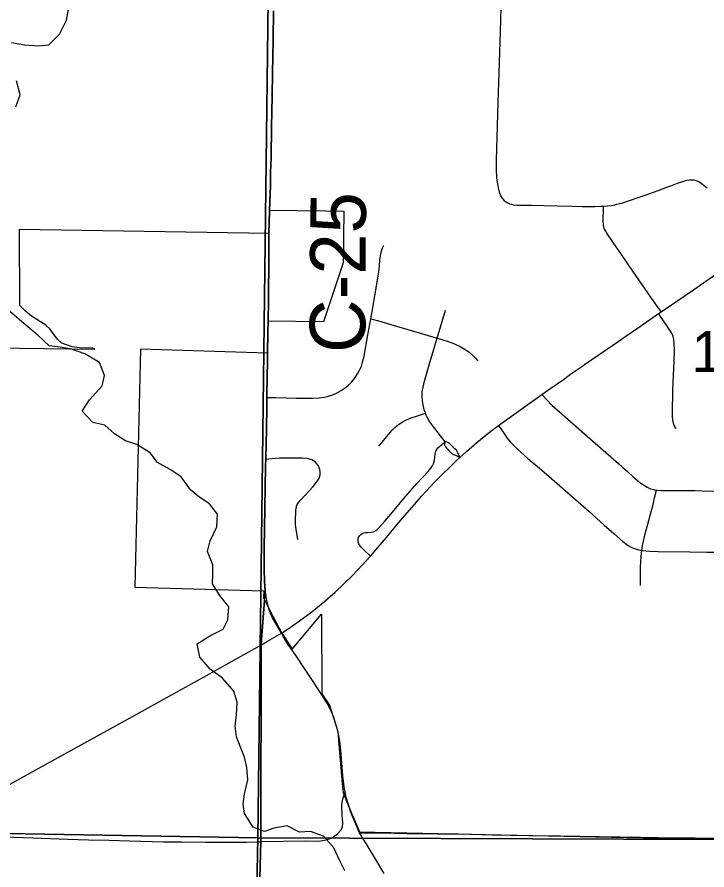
# Model space of a CAD drawing. Extents: x 0 to 34, y 0 to 22.
# Drawn here: x 6.439 to 7.145, y 18.41 to 19.283 of the extents above; entities that cross this region are included whole.
import ezdxf

# ---------------------------------------------------------------- set-up
doc = ezdxf.new("R2010")
doc.units = 0
for name, color, linetype in [('GM_X_City_Street', 7, 'Continuous'), ('GM_X_County_Road', 7, 'Continuous'), ('GM_X_County_Road_Text', 7, 'Continuous'), ('GM_X_County_Text', 7, 'Continuous'), ('GM_X_Minor_River', 7, 'Continuous'), ('GM_X_Section', 7, 'Continuous'), ('GM_X_Section_Text', 7, 'Continuous'), ('GM_X_Township_Road', 7, 'Continuous'), ('GM_X_US_Route', 7, 'Continuous')]:
    doc.layers.add(name, color=color, linetype=linetype)

msp = doc.modelspace()

# ---------------------------------------------------------------- linework, layer by layer
at = {"layer": 'GM_X_City_Street'}
for points in [[(6.93583, 19.09757), (6.93419, 19.10048), (6.93312, 19.10329), (6.93214, 19.1068), (6.93106, 19.11221), (6.93017, 19.11894), (6.9297, 19.12739), (6.92969, 19.1372), (6.9302, 19.1598), (6.93142, 19.19647), (6.93235, 19.2263), (6.93367, 19.26856), (6.9345, 19.29341)], [(6.93583, 19.09757), (6.93672, 19.09643), (6.93762, 19.09547), (6.93833, 19.09492), (6.93948, 19.09416), (6.94067, 19.09344), (6.94199, 19.09285), (6.94342, 19.09225), (6.94509, 19.09178), (6.94701, 19.09135), (6.95012, 19.09094), (6.95364, 19.09083), (6.95711, 19.09077), (6.96165, 19.09071), (6.96562, 19.09073), (6.99178, 19.09011), (7.00669, 19.08974), (7.01726, 19.08943), (7.03029, 19.08948), (7.03673, 19.0897), (7.03918, 19.08988), (7.04324, 19.09019), (7.04689, 19.09062), (7.0487, 19.09088), (7.05072, 19.09126), (7.0529, 19.09178), (7.05883, 19.09342), (7.06591, 19.09571), (7.07353, 19.09833), (7.07869, 19.10007), (7.08289, 19.1016), (7.09052, 19.10433), (7.09525, 19.10606), (7.1039, 19.10932), (7.10802, 19.11072), (7.11499, 19.11328), (7.12034, 19.11523), (7.12456, 19.1165), (7.12713, 19.11684), (7.13039, 19.11683), (7.13164, 19.11668), (7.13299, 19.11644), (7.13488, 19.11594), (7.13668, 19.11508), (7.1404, 19.11253), (7.1453, 19.10877)], [(7.09828, 18.98171), (7.09697, 18.98354), (7.09075, 18.99228), (7.0692, 19.02338), (7.05759, 19.04024), (7.04913, 19.05251), (7.04319, 19.06127), (7.04098, 19.06511), (7.04035, 19.0664), (7.03992, 19.06743), (7.03958, 19.06854), (7.03929, 19.06999), (7.03906, 19.07163), (7.03896, 19.0732), (7.03896, 19.07883), (7.03905, 19.08348), (7.03918, 19.08988)], [(6.6949, 18.89394), (6.70371, 18.89378), (6.72486, 18.89342), (6.74166, 18.89331), (6.7485, 18.89359), (6.75344, 18.8942), (6.75769, 18.89515), (6.76182, 18.89652), (6.76579, 18.8983), (6.77069, 18.90104), (6.77481, 18.90381), (6.77818, 18.90658), (6.78123, 18.90968), (6.78435, 18.91356), (6.78749, 18.91821), (6.7896, 18.92202), (6.79133, 18.92601), (6.79267, 18.93015), (6.79413, 18.93621), (6.79809, 18.95826), (6.80104, 18.9746), (6.8024, 18.98216), (6.80781, 19.01407), (6.80916, 19.02267), (6.8099, 19.02885), (6.81035, 19.03504), (6.81116, 19.04056), (6.81197, 19.04421), (6.81323, 19.04772), (6.81437, 19.04993)], [(6.87714, 18.84857), (6.8724, 18.85468), (6.86425, 18.86544), (6.86092, 18.87002), (6.85896, 18.87328), (6.85731, 18.87671), (6.8569, 18.87779), (6.85597, 18.88028), (6.85483, 18.88457), (6.85392, 18.89019), (6.8536, 18.89524), (6.85374, 18.89967), (6.85447, 18.90468), (6.85596, 18.91079), (6.86152, 18.92989), (6.86887, 18.95474), (6.8767, 18.98109), (6.87736, 18.98348)], [(7.11345, 18.86208), (7.11312, 18.86261), (7.1117, 18.86538), (7.1109, 18.86773), (7.11028, 18.87077), (7.10991, 18.87511), (7.10986, 18.88381), (7.11013, 18.89561), (7.11015, 18.89992), (7.11017, 18.90301), (7.11036, 18.90798), (7.11077, 18.91729), (7.11105, 18.9235), (7.11143, 18.93158), (7.11177, 18.94213), (7.11168, 18.94958), (7.11132, 18.95329), (7.1106, 18.9563), (7.1094, 18.95916), (7.10726, 18.96295), (7.10383, 18.96814), (7.09766, 18.97676), (7.0955, 18.97979)], [(6.80104, 18.9746), (6.80784, 18.97264), (6.82154, 18.96868), (6.85066, 18.96), (6.86887, 18.95474), (6.87151, 18.95398), (6.88218, 18.95073), (6.8868, 18.94893), (6.89238, 18.94624), (6.89666, 18.94373), (6.90124, 18.94054), (6.90504, 18.93736), (6.9081, 18.93429), (6.91043, 18.93139)], [(6.97625, 18.89693), (6.98675, 18.88568), (6.99405, 18.87914), (7.00862, 18.86652), (7.02261, 18.8542), (7.03341, 18.84482), (7.05502, 18.82608), (7.05635, 18.82475), (7.05685, 18.82438), (7.05816, 18.82304), (7.05912, 18.82227), (7.06134, 18.82007), (7.06369, 18.81806), (7.06422, 18.81773), (7.06931, 18.81314), (7.07643, 18.80706), (7.07998, 18.8044), (7.08383, 18.80215), (7.08734, 18.80057), (7.09041, 18.79962), (7.09234, 18.79917), (7.09338, 18.79904), (7.09419, 18.79895), (7.09861, 18.79868), (7.11358, 18.79865), (7.12361, 18.79875), (7.13297, 18.79858), (7.14031, 18.79843), (7.19938, 18.79786)], [(6.8092, 18.84399), (6.82264, 18.86017), (6.8261, 18.8637), (6.82942, 18.86646), (6.83305, 18.86881), (6.83689, 18.87081), (6.84147, 18.87268), (6.84969, 18.8754), (6.8569, 18.87779)], [(6.93157, 18.86522), (6.9371, 18.85742), (6.94068, 18.85235), (6.94369, 18.84865), (6.94616, 18.84611), (6.94955, 18.84279), (6.95427, 18.83823), (6.96163, 18.83161), (6.97362, 18.82163), (6.98072, 18.81554), (7.02425, 18.77746), (7.03998, 18.76332), (7.04966, 18.75458), (7.0591, 18.74656), (7.06449, 18.74248), (7.06759, 18.74063), (7.07092, 18.73925), (7.075, 18.73802), (7.07834, 18.73738), (7.07918, 18.73722), (7.08647, 18.73657), (7.09518, 18.7363), (7.12752, 18.73602), (7.14492, 18.7357), (7.1928, 18.73565)], [(6.80061, 18.73154), (6.79363, 18.7383), (6.79185, 18.74003), (6.78976, 18.74236), (6.78879, 18.74396), (6.78817, 18.74571), (6.78795, 18.74755), (6.78805, 18.74877), (6.78856, 18.75056), (6.78945, 18.75221), (6.79068, 18.7536), (6.79219, 18.75467), (6.79391, 18.75536), (6.79512, 18.75562), (6.79762, 18.75578), (6.80136, 18.75596), (6.80377, 18.75654), (6.806, 18.75761), (6.80749, 18.75872), (6.8093, 18.76043), (6.81544, 18.76749), (6.82163, 18.7745), (6.83266, 18.788), (6.8391, 18.79563), (6.84559, 18.80318), (6.84808, 18.80596), (6.85965, 18.8182), (6.86246, 18.82153), (6.86387, 18.82356), (6.86526, 18.82632), (6.86612, 18.8293), (6.86697, 18.83613), (6.86768, 18.83915), (6.86848, 18.84081), (6.86956, 18.84229), (6.87714, 18.84857)], [(6.89221, 18.83259), (6.88802, 18.83442), (6.88616, 18.83533), (6.88478, 18.83608), (6.88372, 18.83688), (6.88271, 18.8379), (6.87785, 18.84331), (6.87715, 18.84414), (6.87677, 18.8451), (6.87667, 18.84597), (6.87685, 18.84732), (6.87714, 18.84857)], [(6.89221, 18.83259), (6.89172, 18.8337), (6.89014, 18.83734), (6.88945, 18.83863), (6.88902, 18.83932), (6.88859, 18.83989), (6.88696, 18.84155), (6.88529, 18.84322), (6.88207, 18.84636), (6.8806, 18.84757), (6.87994, 18.84793), (6.87915, 18.84824), (6.87807, 18.8485), (6.87714, 18.84857)], [(6.72616, 18.74851), (6.72452, 18.75903), (6.72428, 18.76116), (6.72409, 18.7639), (6.72403, 18.76724), (6.72402, 18.77108), (6.72418, 18.77491), (6.72439, 18.77809), (6.72461, 18.7805), (6.72483, 18.78172), (6.72511, 18.78276), (6.72576, 18.78435), (6.7263, 18.78531), (6.72698, 18.78636), (6.72925, 18.78921), (6.74188, 18.80289), (6.74558, 18.8072), (6.7474, 18.80989), (6.74849, 18.81232), (6.74909, 18.81491), (6.74919, 18.81756), (6.74883, 18.8202), (6.74825, 18.8221), (6.7474, 18.82391), (6.74589, 18.8261), (6.74402, 18.82799), (6.7424, 18.82916), (6.74062, 18.83008), (6.73813, 18.83093), (6.73556, 18.83139), (6.73114, 18.83168), (6.71619, 18.83185), (6.70744, 18.83182), (6.70302, 18.83144), (6.6937, 18.83063)], [(7.0771, 18.70146), (7.07718, 18.72012), (7.07771, 18.7313), (7.07834, 18.73738), (7.07915, 18.74239), (7.08191, 18.75452), (7.09028, 18.78576), (7.09155, 18.7912), (7.09338, 18.79904)]]:
    msp.add_lwpolyline(points, dxfattribs=at)
at = {"layer": 'GM_X_County_Road'}
for p, q in [((7.0955, 18.97979), (7.09828, 18.98171)), ((6.79737, 18.4355), (6.78956, 18.44837))]:
    msp.add_line(p, q, dxfattribs=at)
for points in [[(6.69754, 19.08495), (6.6982, 19.10325), (6.69842, 19.10864), (6.69864, 19.11426), (6.69864, 19.12021), (6.69872, 19.12543), (6.69881, 19.12978), (6.69919, 19.14053), (6.6994, 19.15119), (6.69951, 19.15815), (6.69961, 19.1641), (6.69972, 19.1696), (6.69974, 19.1751), (6.69984, 19.18131), (6.6999, 19.18565), (6.70002, 19.19124), (6.70015, 19.19683), (6.70026, 19.20179), (6.70035, 19.20676), (6.70045, 19.21172), (6.70054, 19.21606), (6.7006, 19.21916), (6.70065, 19.22226), (6.70068, 19.22597), (6.70076, 19.23218), (6.70083, 19.23589), (6.7009, 19.23961), (6.70099, 19.24396), (6.70107, 19.2483), (6.70115, 19.25327), (6.70121, 19.25761), (6.70128, 19.26382), (6.70138, 19.27065), (6.70157, 19.27872), (6.70175, 19.28927)], [(6.69689, 19.06177), (6.69716, 19.07298), (6.69754, 19.08495)], [(7.09828, 18.98171), (7.10672, 18.98754), (7.13134, 19.00434), (7.15434, 19.02016), (7.20178, 19.05322), (7.21864, 19.06479)], [(6.69607, 18.97123), (6.69638, 18.99369), (6.69682, 19.03637), (6.69689, 19.06177)], [(6.99829, 18.91251), (7.00553, 18.9177), (7.01193, 18.92231), (7.01809, 18.92653), (7.01988, 18.92776), (7.03474, 18.93794), (7.05071, 18.94896), (7.06099, 18.95601), (7.07705, 18.96703), (7.0955, 18.97979)], [(6.69564, 18.93867), (6.69589, 18.9607), (6.69607, 18.97123)], [(6.6949, 18.89394), (6.69516, 18.91568), (6.69534, 18.92937), (6.69564, 18.93867)], [(6.97625, 18.89693), (6.98543, 18.90348), (6.99829, 18.91251)], [(6.93157, 18.86522), (6.93548, 18.86818), (6.97625, 18.89693)], [(6.6937, 18.83063), (6.69433, 18.86094), (6.69471, 18.88395), (6.69489, 18.89266), (6.6949, 18.89394)], [(6.89221, 18.83259), (6.89888, 18.83872), (6.90965, 18.848), (6.92264, 18.85847), (6.93157, 18.86522)], [(6.69326, 18.69505), (6.69244, 18.70545), (6.69224, 18.71726), (6.69216, 18.73965), (6.69238, 18.75894), (6.69293, 18.78071), (6.69354, 18.823), (6.6937, 18.83063)], [(6.82472, 18.75973), (6.83349, 18.77026), (6.84562, 18.78439), (6.85337, 18.79332), (6.86669, 18.80764), (6.88888, 18.82952), (6.89221, 18.83259)], [(6.80061, 18.73154), (6.80632, 18.73792), (6.8172, 18.7507), (6.82472, 18.75973)], [(6.70946, 18.65252), (6.71642, 18.65715), (6.72807, 18.66532), (6.74054, 18.67461), (6.75411, 18.68554), (6.76441, 18.69456), (6.77355, 18.703), (6.78241, 18.71175), (6.79223, 18.72216), (6.80061, 18.73154)], [(6.70946, 18.65252), (6.70468, 18.66073), (6.70042, 18.66841), (6.6983, 18.67301), (6.69699, 18.67657), (6.69547, 18.68206), (6.69465, 18.68606), (6.69384, 18.69007), (6.69326, 18.69505)], [(6.68917, 18.64087), (6.69541, 18.64445), (6.70946, 18.65252)], [(6.72036, 18.63535), (6.71625, 18.64148), (6.71159, 18.64885), (6.70946, 18.65252)], [(6.35793, 18.44665), (6.36223, 18.45067), (6.37078, 18.45782), (6.3805, 18.46552), (6.39004, 18.47243), (6.39983, 18.47899), (6.41244, 18.48689), (6.43175, 18.49816), (6.46106, 18.51451), (6.54114, 18.55854), (6.58302, 18.58174), (6.63577, 18.61095), (6.65918, 18.62387), (6.67924, 18.63516), (6.68917, 18.64087)], [(6.75082, 18.58957), (6.74074, 18.60519), (6.73312, 18.61657), (6.72534, 18.62838), (6.72036, 18.63535)], [(6.77468, 18.49006), (6.77441, 18.49121), (6.77328, 18.498), (6.77231, 18.5067), (6.77019, 18.53274), (6.76915, 18.54197), (6.76791, 18.54927), (6.76683, 18.55408), (6.76568, 18.55824), (6.76306, 18.5664), (6.761, 18.57152), (6.75863, 18.57653), (6.75602, 18.58143), (6.75082, 18.58957)], [(6.77246, 18.4584), (6.77203, 18.46275), (6.77185, 18.46648), (6.77138, 18.47516), (6.77146, 18.47732), (6.77159, 18.47891), (6.7719, 18.4808), (6.77246, 18.48305), (6.77468, 18.49006)], [(6.78956, 18.44837), (6.7836, 18.46195), (6.78138, 18.46752), (6.78103, 18.4684), (6.77784, 18.47788), (6.77594, 18.48449), (6.77468, 18.49006)], [(6.68875, 18.43925), (6.73412, 18.43992), (6.74791, 18.43982), (6.75528, 18.44107), (6.76131, 18.44308), (6.76686, 18.44711), (6.77069, 18.45113), (6.77203, 18.45448), (6.77246, 18.4584)], [(6.35793, 18.44665), (6.36634, 18.44606), (6.37341, 18.44573), (6.39156, 18.44504), (6.40513, 18.44458), (6.41716, 18.44425), (6.43567, 18.44368), (6.45502, 18.44294), (6.49085, 18.44171), (6.51197, 18.44119), (6.53308, 18.44062), (6.55419, 18.44002), (6.58898, 18.43913), (6.60762, 18.43887), (6.63185, 18.43866), (6.65298, 18.4386), (6.67388, 18.43883), (6.68534, 18.43905), (6.68712, 18.43912), (6.68875, 18.43925)], [(6.8146, 18.40643), (6.80622, 18.42092), (6.79737, 18.4355)]]:
    msp.add_lwpolyline(points, dxfattribs=at)
at = {"layer": 'GM_X_County_Text'}
for points in [[(6.6835, 18.25001), (6.68851, 18.43981), (6.68894, 18.64142), (6.69302, 18.69561), (6.69221, 18.70601), (6.692, 18.71781), (6.69192, 18.7402), (6.69214, 18.75949), (6.69269, 18.78126), (6.6933, 18.82356), (6.69346, 18.83118), (6.69409, 18.8615), (6.69447, 18.88451), (6.69465, 18.89321), (6.69467, 18.89449), (6.69492, 18.91623), (6.69511, 18.92992), (6.69541, 18.93923), (6.69566, 18.96125), (6.69583, 18.97178), (6.69614, 18.99425), (6.69658, 19.03692), (6.69665, 19.06232), (6.69692, 19.07354), (6.69731, 19.08551), (6.69797, 19.10381), (6.69818, 19.1092), (6.69841, 19.11481), (6.6984, 19.12076), (6.69848, 19.12599), (6.69857, 19.13033), (6.69895, 19.14108), (6.69916, 19.15175), (6.69927, 19.15871), (6.69938, 19.16466), (6.69948, 19.17016), (6.6995, 19.17565), (6.6996, 19.18186), (6.69966, 19.18621), (6.69978, 19.19179), (6.69992, 19.19738), (6.70002, 19.20235), (6.70012, 19.20731), (6.70021, 19.21227), (6.7003, 19.21661), (6.70037, 19.21971), (6.70041, 19.22281), (6.70045, 19.22653), (6.70053, 19.23273), (6.70059, 19.23645), (6.70066, 19.24017), (6.70075, 19.24451), (6.70083, 19.24885), (6.70091, 19.25382), (6.70097, 19.25816), (6.70104, 19.26437), (6.70115, 19.27121), (6.70133, 19.27928), (6.70151, 19.28983)], [(6.70151, 19.28983), (6.70133, 19.27928), (6.70115, 19.27121), (6.70104, 19.26437), (6.70097, 19.25816), (6.70091, 19.25382), (6.70083, 19.24885), (6.70075, 19.24451), (6.70066, 19.24017), (6.70059, 19.23645), (6.70053, 19.23273), (6.70045, 19.22653), (6.70041, 19.22281), (6.70037, 19.21971), (6.7003, 19.21661), (6.70021, 19.21227), (6.70012, 19.20731), (6.70002, 19.20235), (6.69992, 19.19738), (6.69978, 19.19179), (6.69966, 19.18621), (6.6996, 19.18186), (6.6995, 19.17565), (6.69948, 19.17016), (6.69938, 19.16466), (6.69927, 19.15871), (6.69916, 19.15175), (6.69895, 19.14108), (6.69857, 19.13033), (6.69848, 19.12599), (6.6984, 19.12076), (6.69841, 19.11481), (6.69818, 19.1092), (6.69797, 19.10381), (6.69731, 19.08551), (6.69692, 19.07354), (6.69665, 19.06232), (6.69658, 19.03692), (6.69614, 18.99425), (6.69583, 18.97178), (6.69566, 18.96125), (6.69541, 18.93923), (6.69511, 18.92992), (6.69492, 18.91623), (6.69467, 18.89449), (6.69465, 18.89321), (6.69447, 18.88451), (6.69409, 18.8615), (6.69346, 18.83118), (6.6933, 18.82356), (6.69269, 18.78126), (6.69214, 18.75949), (6.69192, 18.7402), (6.692, 18.71781), (6.69221, 18.70601), (6.69302, 18.69561), (6.68894, 18.64142), (6.68851, 18.43981), (6.6835, 18.25001)]]:
    msp.add_lwpolyline(points, dxfattribs=at)
at = {"layer": 'GM_X_Minor_River'}
for points in [[(6.43336, 19.25736), (6.44659, 19.2552), (6.46136, 19.25416), (6.47162, 19.2551), (6.48244, 19.26589), (6.48954, 19.28018), (6.49207, 19.29341)], [(6.43778, 19.19162), (6.44218, 19.20367), (6.43829, 19.21817)], [(6.44787, 18.9679), (6.42661, 18.98615)], [(6.63584, 18.78514), (6.6261, 18.7914), (6.6164, 18.79956), (6.60679, 18.81264), (6.59556, 18.82007), (6.58281, 18.82753), (6.57504, 18.83716), (6.56155, 18.84578), (6.54987, 18.84942), (6.53863, 18.85685), (6.52894, 18.86576), (6.51648, 18.86828), (6.50571, 18.87987), (6.51314, 18.89149), (6.52593, 18.90605), (6.52841, 18.91662), (6.52335, 18.92962), (6.50836, 18.93864), (6.4948, 18.94346), (6.48309, 18.94558), (6.47173, 18.94694), (6.46056, 18.95741), (6.44787, 18.9679)], [(6.77458, 18.40945), (6.76946, 18.41941), (6.76328, 18.43281), (6.75251, 18.44479), (6.73933, 18.44959), (6.72794, 18.44906), (6.71555, 18.45537), (6.70186, 18.45298), (6.69231, 18.44975), (6.68064, 18.45415), (6.67181, 18.46798), (6.67048, 18.47749), (6.67182, 18.48809), (6.67513, 18.50244), (6.67423, 18.51498), (6.67179, 18.52565), (6.66781, 18.53598), (6.66347, 18.54668), (6.66216, 18.55733), (6.66352, 18.56907), (6.66415, 18.58196), (6.66096, 18.5934), (6.64908, 18.60653), (6.63675, 18.61588), (6.62599, 18.62823), (6.62321, 18.64157), (6.63627, 18.65004), (6.65004, 18.6566), (6.65478, 18.66638), (6.6558, 18.67964), (6.64654, 18.6912), (6.63881, 18.70312), (6.63938, 18.71297), (6.63918, 18.72246), (6.63376, 18.73623), (6.63662, 18.74718), (6.64335, 18.76146), (6.64397, 18.77435), (6.63584, 18.78514)]]:
    msp.add_lwpolyline(points, dxfattribs=at)
at = {"layer": 'GM_X_Section'}
for points in [[(5.68333, 19.46665), (6.6975, 19.43966), (6.68531, 18.44295), (5.65349, 18.46087)], [(6.69788, 19.47262), (7.63985, 19.45485), (7.62229, 18.4397), (6.68531, 18.44295), (6.6975, 19.43966)], [(5.65349, 18.46087), (6.68531, 18.44295), (6.66543, 17.44151), (5.65514, 17.45551)], [(6.68531, 18.44295), (7.62229, 18.4397), (7.606, 17.42984), (6.66543, 17.44151)]]:
    msp.add_lwpolyline(points, close=True, dxfattribs=at)
at = {"layer": 'GM_X_Township_Road'}
msp.add_lwpolyline([(6.78956, 18.44837), (6.81244, 18.44825), (6.83779, 18.4477), (6.86924, 18.44731), (6.89091, 18.44704), (6.90436, 18.44674), (6.92486, 18.4463), (6.96278, 18.44561), (6.99509, 18.44504), (7.03488, 18.44433), (7.07715, 18.44373), (7.1132, 18.44322), (7.13309, 18.44301), (7.18469, 18.44253), (7.23477, 18.44162)], dxfattribs=at)
at = {"layer": 'GM_X_US_Route'}
msp.add_lwpolyline([(6.18274, 18.95135), (6.44148, 18.94463), (6.51855, 18.9436), (6.51642, 18.94441), (6.5025, 18.94478), (6.49535, 18.9459), (6.48481, 18.94965), (6.48067, 18.95341), (6.47653, 18.95829), (6.47276, 18.96393), (6.46824, 18.96807), (6.45356, 18.97708), (6.4471, 18.98277), (6.4419, 18.98809), (6.44134, 19.06624), (6.69694, 19.06211), (6.69747, 19.08567), (6.75451, 19.08499), (6.77345, 19.08474), (6.7727, 19.03168), (6.75865, 18.98969), (6.7525, 18.9713), (6.69565, 18.97204), (6.69519, 18.93948), (6.56512, 18.94328), (6.55965, 18.69967), (6.69141, 18.69604), (6.69111, 18.68892), (6.69658, 18.67837), (6.70121, 18.66945), (6.70956, 18.65337), (6.72038, 18.63633), (6.75046, 18.67218), (6.75084, 18.5905), (6.75858, 18.57888), (6.76247, 18.56694), (6.76734, 18.55197), (6.76812, 18.54265), (6.77181, 18.49868), (6.7726, 18.48934), (6.78131, 18.46824), (6.78957, 18.4492), (7.09571, 18.44272), (7.12661, 18.44206), (7.15999, 18.442)], dxfattribs=at)

# ---------------------------------------------------------------- texts
at = {"layer": 'GM_X_County_Road_Text'}
msp.add_text('C-25', height=0.056818, rotation=89.65567, dxfattribs=at).set_placement((6.7952, 18.93941))
at = {"layer": 'GM_X_Section_Text'}
msp.add_text('19', height=0.041856, rotation=0.00001, dxfattribs=at).set_placement((7.1294, 18.92008))

doc.saveas('drawing.dxf')
